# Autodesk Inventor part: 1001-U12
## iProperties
Created: 2007-03
Part Number: 1001-U12
Document SubType Name: Modeling
Designer: Andy Moles
Material: ABS Plastic
Density: 1.06 g/cm^3
Author: Andy Moles
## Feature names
1. Base1
